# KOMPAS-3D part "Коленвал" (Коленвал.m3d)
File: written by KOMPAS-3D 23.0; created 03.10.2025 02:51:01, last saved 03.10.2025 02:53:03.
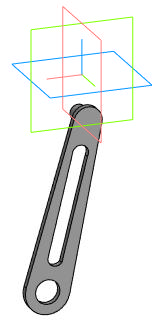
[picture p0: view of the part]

Document properties: Автор: Inspektor_Kot; Полное имя файла: I:\Autodesk Inventor Projects\ИМ-ИТ ЦД\Вариант 13\Коленвал.m3d

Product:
- Part/product: Коленвал
    Масса: 0.003949

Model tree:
1. Эскиз:1  (with: Элемент выдавливания:1)
2. Элемент выдавливания:1
     Расстояние 1 = -10
3. Эскиз:2  (with: Элемент выдавливания:1, Скругление:2)
4. Элемент выдавливания:2
     Расстояние 1 = 3
5. Эскиз:3  (with: Элемент выдавливания:2, Элемент выдавливания:4)
6. Элемент выдавливания:3
     Расстояние 2 = 3
7. Эскиз:4  (with: Элемент выдавливания:2, Элемент выдавливания:4)
8. Элемент выдавливания:4
     Расстояние 2 = 13

Referenced files in I:\Autodesk Inventor Projects\ИМ-ИТ ЦД\Вариант 13\: Стенд ДВС.a3d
